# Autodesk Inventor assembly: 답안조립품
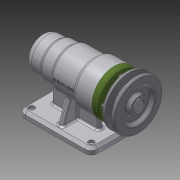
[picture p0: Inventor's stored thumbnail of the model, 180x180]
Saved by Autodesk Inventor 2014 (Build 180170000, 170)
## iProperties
Created: 2016-06
Part Number: 답안조립품
Document SubType Name: Assembly
Designer: USER
Author: USER
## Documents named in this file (12)
- C:\Users\USER\Desktop\460607V1026\답안조립품.iam
- C:\Users\USER\Desktop\460607V1026\본체.ipt
- C:\Users\USER\Desktop\460607V1026\베어링 51202.ipt
- C:\Users\USER\Desktop\460607V1026\어댑터슬리브.ipt
- C:\Users\USER\Desktop\460607V1026\베어링 6004.ipt
- C:\Users\USER\Desktop\460607V1026\커버.ipt
- C:\Users\USER\Desktop\460607V1026\축.ipt
- C:\Users\USER\Desktop\460607V1026\볼트 M4 x 12.ipt
- C:\Users\USER\Desktop\460607V1026\키 5 x 5 x 16.ipt
- C:\Users\USER\Desktop\460607V1026\오일 실.ipt
- C:\Users\USER\Desktop\460607V1026\V벨트풀리.ipt
- C:\Users\USER\Desktop\460607V1026\멈춤나사 M3x8.ipt
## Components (6 placed, 2 different names)
1. V벨트풀리:1
2. ISO 4762 M4 x 12:5
3. ISO 4762 M4 x 12:1
4. ISO 4762 M4 x 12:2
5. ISO 4762 M4 x 12:3
6. ISO 4762 M4 x 12:4
